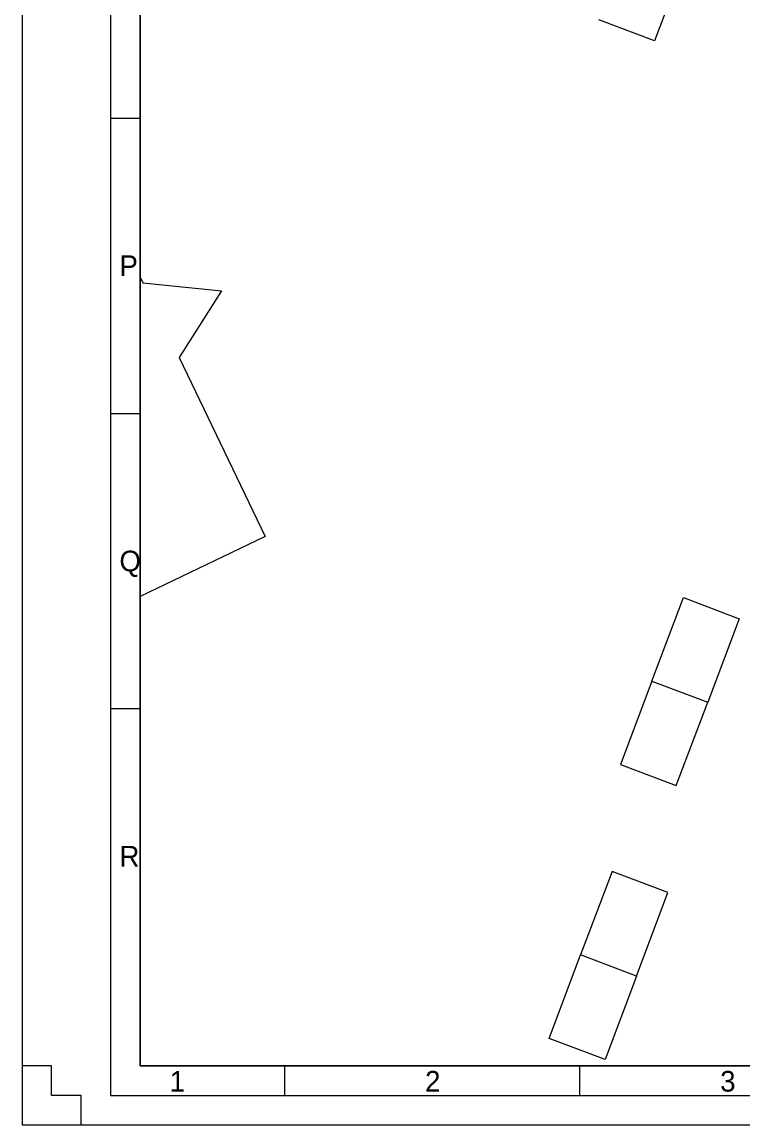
# Model space of a CAD drawing. Extents: x 192672 to 192910, y 446344 to 446512.
# Drawn here: x 192671.74 to 192696.17, y 446343.56 to 446380.91 of the extents above; entities that cross this region are included whole.
import ezdxf

# ---------------------------------------------------------------- set-up
doc = ezdxf.new("R2010")
doc.units = 0
for name, color, linetype in [('1010 viewport', 7, 'Continuous'), ('pand op maaiveld vlak', 7, 'Continuous'), ('X-XX-AL-TEKENBLAD-S', 7, 'Continuous')]:
    doc.layers.add(name, color=color, linetype=linetype)

msp = doc.modelspace()

# ---------------------------------------------------------------- linework, layer by layer
at = {"layer": '1010 viewport'}
msp.add_lwpolyline([(192675.743, 446509.756), (192860.643, 446509.756), (192860.643, 446345.556), (192675.743, 446345.556)], close=True, dxfattribs=at)
at = {"layer": 'pand op maaiveld vlak'}
for p, q in [((192693.087, 446358.59), (192694.977, 446357.877)), ((192692.56, 446348.6), (192690.67, 446349.313))]:
    msp.add_line(p, q, dxfattribs=at)
for points in [[(192692.365, 446383.812), (192694.243, 446383.097), (192693.169, 446380.274), (192691.291, 446380.989)], [(192675.743, 446372.272), (192675.837, 446372.077), (192678.502, 446371.807), (192677.062, 446369.552), (192679.976, 446363.486), (192675.743, 446361.453)], [(192693.087, 446358.59), (192694.152, 446361.415), (192696.042, 446360.703), (192694.977, 446357.877)], [(192693.087, 446358.59), (192692.021, 446355.764), (192693.911, 446355.051), (192694.977, 446357.877)], [(192692.56, 446348.6), (192693.625, 446351.426), (192691.735, 446352.138), (192690.67, 446349.313)], [(192692.56, 446348.6), (192691.495, 446345.774), (192689.604, 446346.487), (192690.67, 446349.313)]]:
    msp.add_lwpolyline(points, dxfattribs=at)
at = {"layer": 'X-XX-AL-TEKENBLAD-S'}
for p, q in [((192671.743, 446511.756), (192671.743, 446343.556)), ((192674.743, 446510.756), (192674.743, 446344.556)), ((192674.743, 446377.656), (192675.743, 446377.656)), ((192674.743, 446367.656), (192675.743, 446367.656)), ((192674.743, 446357.656), (192675.743, 446357.656)), ((192680.643, 446344.556), (192680.643, 446345.556)), ((192690.643, 446344.556), (192690.643, 446345.556)), ((192674.743, 446344.556), (192908.543, 446344.556)), ((192671.743, 446343.556), (192909.543, 446343.556))]:
    msp.add_line(p, q, dxfattribs=at)
msp.add_lwpolyline([(192675.743, 446345.556), (192907.543, 446345.556), (192907.543, 446509.756), (192675.743, 446509.756)], close=True, dxfattribs=at)
msp.add_lwpolyline([(192671.743, 446345.556), (192671.743, 446343.556), (192673.743, 446343.556), (192673.743, 446344.556), (192672.743, 446344.556), (192672.743, 446345.556), (192671.743, 446345.556)], dxfattribs=at)

# ---------------------------------------------------------------- texts
for s, p in [('P', (192675.043, 446372.306)), ('Q', (192675.043, 446362.306)), ('R', (192675.043, 446352.306)), ('1', (192676.745, 446344.685)), ('2', (192685.399, 446344.685)), ('3', (192695.398, 446344.685))]:
    msp.add_text(s, height=0.7, dxfattribs=at).set_placement(p)

doc.saveas('drawing.dxf')
